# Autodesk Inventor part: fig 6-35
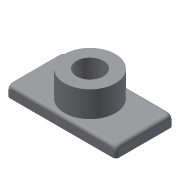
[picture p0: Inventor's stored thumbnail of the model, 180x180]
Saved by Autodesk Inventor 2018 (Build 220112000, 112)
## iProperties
Created: 2004-05
Part Number: fig 6-35
Document SubType Name: Modeling
Designer: CADCIM Technologies
Manufacturer: Standard
Standards Organization: Custom
Density: 1 g/cm^3
Material: Generic
Appearance: Default
Author: CADCIM Technologies
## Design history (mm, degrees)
sketch "Sketch1"
  geometry: L1 (-39.276, -18.692)-(33.721, -18.692); L2 (33.721, -18.692)-(33.721, 19.728); L3 (33.721, 19.728)-(-39.276, 19.728); L4 (-39.276, 19.728)-(-39.276, -18.692)
  constraints: 8 end point, 2 parallel, 1 horizontal, 1 perpendicular
extrude "Extrusion1" new body sketch "Sketch1" distance "d0" = 7.5; taper "d1" = 0 deg
sketch "Sketch2"
  geometry: C1 r 17 at (-2.778, 0.518)
  constraints: 1 centre point
  dimensions: "d16" = 34 diameter of C1
extrude "Extrusion2" join sketch "Sketch2" distance "d3" = 17.25; taper "d4" = 0 deg
hole "Hole1" diameter "d8" = 18; stored, may be unused: countersink angle "d12" = 90 deg, drill point angle "d14" = 118 deg; dims "d6" = 10, "d7" = 10, "d9" = 6, "d10" = 4, "d11" = 2, "d13" = 8
fillet "Fillet4" dims "d17" = 2
body "Solid1"
